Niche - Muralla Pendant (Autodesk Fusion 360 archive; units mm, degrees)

design "Murralla" references "Niche - Chief Architect - Luxe Single Pendant Cordset", "Luxe Single Pendant Cordset - 4ft Standard", "Muralla"
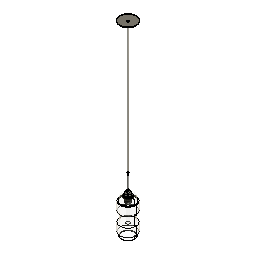
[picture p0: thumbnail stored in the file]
external_derived "ExternalDerived1"
external_derived "ExternalDerived2" bodies "Socket Body", "Shade Ring", "Shade Ring +Collar", "Socket", "Body1", "Metal Strain Relief", "Fabric Cord (1)", "Stem (Threaded)"
move "Move1"
external_derived "ExternalDerived3" bodies "T9-Bulb"
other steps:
derived_base_feature "Derived Base Feature1" bodies "Body8"
derived_base_feature "Derived Base Feature2" bodies "Socket Body", "Shade Ring", "Shade Ring +Collar", "Socket", "Body1", "Metal Strain Relief", "Fabric Cord (1)", "Stem (Threaded)"
derived_base_feature "Derived Base Feature3" bodies "T9-Bulb"
named bodies: "Body8", "Socket Body", "Shade Ring", "Shade Ring +Collar", "Socket", "Body1", "Metal Strain Relief", "Fabric Cord (1)", "Stem (Threaded)", "Cap (Threaded)", "T9-Bulb"

design "Luxe Single Pendant Cordset - 4ft Standard" references "Luxe Canopy - Single Pendant Cordset"
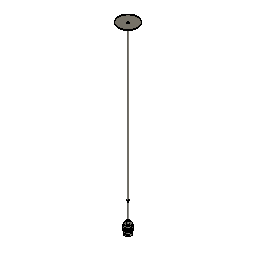
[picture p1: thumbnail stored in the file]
external_derived "ExternalDerived2" bodies "Cap (Threaded)"
move "Move1"
move "Move2"
offset_faces "OffsetFaces1" distance 1051.56
move "Move3"
move "Move4"
move "Move5"
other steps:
derived_base_feature "Derived Base Feature9" bodies "Socket Body", "Shade Ring", "Shade Ring +Collar", "Socket"
derived_base_feature "Derived Base Feature10" bodies "Body1"
derived_base_feature "Derived Base Feature12" bodies "Metal Strain Relief"
derived_base_feature "Derived Base Feature13" bodies "Fabric Cord (1)"
derived_base_feature "Derived Base Feature14" bodies "Stem (Threaded)"
derived_base_feature "Derived Base Feature15" bodies "Cap 9Threaded)", "Cap (Threaded)"
named bodies: "Socket Body", "Shade Ring", "Shade Ring +Collar", "Socket", "Metal Strain Relief", "Fabric Cord (1)", "Stem (Threaded)", "Cap 9Threaded)", "Body1", "Cap (Threaded)", "5M Set Screw"

design "Luxe Canopy - Single Pendant Cordset" references "Luxe Cordset", "Canopy Mounting Bar Screw", "M5 Set Screw", "Plastic Strain Relief", "Canopy Mounting Bar"
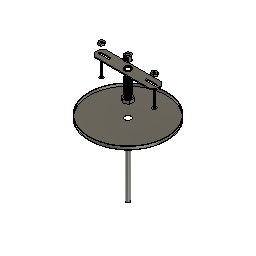
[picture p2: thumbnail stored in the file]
sketch "Sketch1" plane through (0, 0, 0) normal (0, 0, 1) x axis (1, 0, 0)
  circle C1 centre (0, 0) radius 63.5
  point P1 (0, 0)
  point P2 (0, 0)
  coincident P1 P2
  dimension "d1" diameter C1 = 127
extrude "Extrude1" new body sketch "Sketch1" along normal blind 5.08
shell "Shell1" innerThickness 0.762
hole "Hole1" HoleDepth 35.56 HoleDiameter 10.16 TipAngle 118
component_from_bodies "Body->Comp1"
component_insert "Component Insert1"
component_insert "Component Insert2"
component_insert "Component Insert3"
sketch "Sketch2" plane through (0, 0, 0) normal (0, 0, 1) x axis (1, 0, 0)
  circle C1 centre (0, 0) radius 3.175
  point P1 (0, 0)
  point P2 (0, 0)
  coincident P1 P2
  dimension "d8" diameter C1 = 6.35
extrude "Extrude2" new body sketch "Sketch2" along normal blind 127 and against normal blind 127 bodies "Fabric Cord"
component_insert "Component Insert4"
component_insert "Component Insert5"
position "Position1"
sketch "Sketch3" plane through (0, 0, 0.762) normal (0, 0, 1) x axis (-1, 0, 0)
  circle C1 centre (-0.0475, 0.2257) radius 5.08
  circle C2 centre (0, 0) radius 62.738
  circle C3 centre (0, 0) radius 4.826
  concentric C2 C3
  dimension "d13" diameter C3 = 9.652
extrude "Extrude3" new body sketch "Sketch3" profile of C3 along normal blind 25.4 bodies "Threaded Nipple"
shell "Shell2" innerThickness 1.27
thread "Thread1"
sketch "Sketch5" plane through (0, 0, 127) normal (0, 0, 1) x axis (-1, 0, 0)
  line L1 (-6.8191, 3.937) -> (0, 7.874)
  line L2 (-6.8191, -3.937) -> (-6.8191, 3.937)
  line L3 (0, -7.874) -> (-6.8191, -3.937)
  line L4 (6.8191, -3.937) -> (0, -7.874)
  line L5 (6.8191, 3.937) -> (6.8191, -3.937)
  line L6 (0, 7.874) -> (6.8191, 3.937)
  circle C1 centre (0, 0) radius 3.175
  point P2 (0, 0)
  point P9 (0, 0)
  point P3 (0, 7.874)
  coincident P2 P9
  dimension "d20" distance P3 P9 = 7.874
extrude "Extrude4" new body sketch "Sketch5" along normal blind 5.08 bodies "Hex Nut"
move "Move1"
thread "Thread2"
move "Move2" TranslateX 0 TranslateY 0 TranslateZ -55.88
move "Move3" TranslateX 0 TranslateY 0 TranslateZ 60.96
position "Position2"
sketch "Sketch6" plane through (0, 0, 0) normal (0, 0, 1) x axis (1, 0, 0)
  circle C1 centre (0, 0) radius 9.525
  point P1 (0, 0)
  point P2 (0, 0)
  coincident P1 P2
  dimension "d29" diameter C1 = 19.05
extrude "Extrude5" new body sketch "Sketch6" along normal blind 16.129 bodies "Metal Strain Relief"
move "Move4" TranslateX 0 TranslateY 0 TranslateZ -86.36
hole "Hole2" HoleDepth 10.16 HoleDiameter 5.08 TipAngle 118
hole "Hole3" HoleDepth 4.064 HoleDiameter 7.62 TipAngle 180
hole "Hole4" HoleDepth 12.192 HoleDiameter 9.144 TipAngle 180
thread "Thread3" ThreadOffset 0 ThreadLength 6.096
move "Move1" TranslateX 0 TranslateY 0 TranslateZ 68.58
move "Move5" TranslateX 0 TranslateY 0 TranslateZ 138.43
component_insert "Component Insert6"
external_derived "ExternalDerived1" bodies "5M Set Screw"
move "Move6" TranslateX 0 TranslateY 0 TranslateZ -185.42
copy_paste_bodies "CopyPasteBodies1"
move "Move7" TranslateX 0 TranslateY 0 TranslateZ -12.7
offset_faces "OffsetFaces1" distance -152.4
move "Move8"
component_from_bodies "Body->Comp2"
component_from_bodies "Body->Comp3"
component_from_bodies "Body->Comp4"
component_from_bodies "Body->Comp5"
hole "Hole1" HoleDepth 25.4 HoleDiameter 6.35 TipAngle 180
sketch "Sketch7" plane through (0, 0, 0) normal (0, 0, 1) x axis (1, 0, 0)
  line L1 (49.784, 3.9595) -> (52.07, 0)
  line L2 (45.212, 3.9595) -> (49.784, 3.9595)
  line L3 (42.926, 0) -> (45.212, 3.9595)
  line L4 (45.212, -3.9595) -> (42.926, 0)
  line L5 (49.784, -3.9595) -> (45.212, -3.9595)
  line L6 (52.07, 0) -> (49.784, -3.9595)
  point P2 (52.07, 0)
  point P8 (47.498, 0)
  dimension "d63" distance P2 P8 = 4.572
extrude "Extrude6" new body sketch "Sketch7" along normal blind 3.175 bodies "Mounting Hex Nut"
hole "Hole5" HoleDepth 25.4 HoleDiameter 3.81 TipAngle 180
thread "Thread4"
move "Move9"
component_from_bodies "Body->Comp6"
copy_paste "CopyPaste1"
move "Move10"
derived_base_feature "Derived Base Feature3" bodies "Stem (Threaded)", "Cap 9Threaded)"
move "Move11"
component_from_bodies "Body->Comp7"
component_from_bodies "Body->Comp8"
component_from_bodies "Body->Comp9"
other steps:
base_feature "Base Feature1"
base_feature "Base Feature1" bodies "Stem (Threaded)"
base_feature "Base Feature1" bodies "Cap 9Threaded)"
base_feature "Base Feature1" bodies "Fabric Cord"
base_feature "Base Feature1" bodies "Metal Strain Relief"
base_feature "Base Feature1" bodies "Mounting Hex Nut"
base_feature "Base Feature1" bodies "Hex Nut"
base_feature "Base Feature1" bodies "Fabric Cord (1)"
base_feature "Base Feature1" bodies "Threaded Nipple"
derived_base_feature "Derived Base Feature1" bodies "Socket Body", "Shade Ring", "Shade Ring +Collar", "Socket", "Rigid Stem"
derived_base_feature "Derived Base Feature2" bodies "5M Set Screw"
base_feature "Base Feature1" bodies "Fabric Cord", "Fabric Cord (1)"
create_component "CreateComponent1"
remove_body "RemoveBody1"
create_component "CreateComponent2"
remove_body "RemoveBody2"
create_component "CreateComponent3"
remove_body "RemoveBody3"
create_component "CreateComponent4"
remove_body "RemoveBody4"
create_component "CreateComponent5"
remove_body "RemoveBody5"
create_component "CreateComponent6"
remove_body "RemoveBody6"
create_component "CreateComponent7"
remove_body "RemoveBody7"
create_component "CreateComponent8"
remove_body "RemoveBody8"
create_component "CreateComponent9"
remove_body "RemoveBody9"
named bodies: "Fabric Cord", "Threaded Nipple", "Hex Nut", "Metal Strain Relief", "Socket Body", "Shade Ring", "Shade Ring +Collar", "Socket", "Rigid Stem", "5M Set Screw", "Fabric Cord (1)", "Mounting Hex Nut", "Stem (Threaded)", "Cap 9Threaded)"

design "Muralla" references "Niche_Muralla_Single_Pendant"
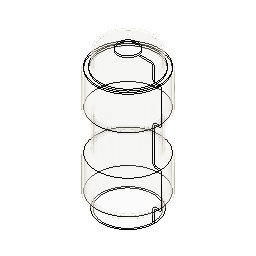
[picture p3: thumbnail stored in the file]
external_derived "ExternalDerived"
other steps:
derived_base_feature "Derived Base Feature" bodies "Body8"
named bodies: "Body8"

design "M5 Set Screw"
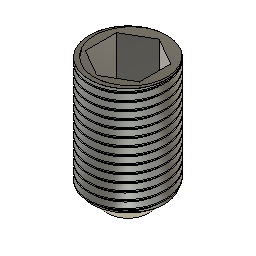
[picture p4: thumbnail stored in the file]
sketch "Sketch1" plane through (0, 0, 0) normal (0, 0, 1) x axis (1, 0, 0)
  circle C1 centre (0, 0) radius 2.5
  point P1 (0, 0)
  point P2 (0, 0)
  coincident P1 P2
  dimension "d1" diameter C1 = 5
extrude "Extrude1" new body sketch "Sketch1" along normal blind 8
sketch "Sketch2" plane through (0, 0, 8) normal (0, 0, 1) x axis (-1, 0, 0)
  line L1 (-1.7321, 1) -> (0, 2)
  line L2 (-1.7321, -1) -> (-1.7321, 1)
  line L3 (0, -2) -> (-1.7321, -1)
  line L4 (1.7321, -1) -> (0, -2)
  line L5 (1.7321, 1) -> (1.7321, -1)
  line L6 (0, 2) -> (1.7321, 1)
  circle C1 centre (0, 0) radius 2.5
  point P2 (0, 0)
  point P9 (0, 0)
  coincident P2 P9
extrude "Extrude2" cut sketch "Sketch2" profile of L1 L2 L3 L4 L5 L6 against normal blind 3
thread "Thread1" ThreadOffset 0.99 ThreadLength 7
chamfer "Chamfer1" distance 1.15

design "Luxe Cordset" references "M5 Set Screw"
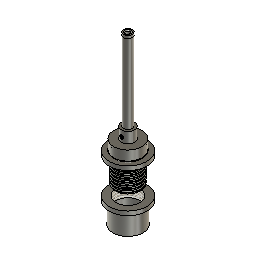
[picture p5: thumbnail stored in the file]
sketch "Sketch1" plane through (0, 0, 0) normal (0, 0, 1) x axis (1, 0, 0)
  circle C1 centre (0, 0) radius 20.6
  point P1 (0, 0)
  point P2 (0, 0)
  coincident P1 P2
  dimension "d11" diameter C1 = 41.2
extrude "Extrude1" new body sketch "Sketch1" along normal blind 14 bodies "Socket Body"
sketch "Sketch2" plane through (0, 0, 14) normal (0, 0, 1) x axis (-1, 0, 0)
  circle C1 centre (0, 0) radius 20.6
  circle C2 centre (0, 0) radius 9.6
  concentric C1 C2
  dimension "d3" diameter C2 = 19.2
extrude "Extrude2" add sketch "Sketch2" profile of C2 along normal blind 15.75
sketch "Sketch3" plane through (0, 0, 29.75) normal (0, 0, 1) x axis (-1, 0, 0)
  circle C1 centre (0, 0) radius 9.6
  circle C2 centre (0, 0) radius 5.75
  concentric C1 C2
  dimension "d6" diameter C2 = 11.5
extrude "Extrude3" new body sketch "Sketch3" profile of C2 along normal blind 114 bodies "Rigid Stem"
move "Move1"
sketch "Sketch4" plane through (0, 0, 203.75) normal (0, 0, 1) x axis (-1, 0, 0)
  circle C1 centre (0, 0) radius 5.75
  circle C2 centre (0, 0) radius 27.5
  dimension "d10" diameter C2 = 55
extrude "Extrude4" new body sketch "Sketch4" profile of C2 along normal blind 6 bodies "Shade Ring"
hole "Hole1" HoleDepth 25 HoleDiameter 42.75 TipAngle 118
sketch "Sketch5" plane through (0, 0, 0) normal (0, 0, 1) x axis (1, 0, 0)
  circle C1 centre (0, 0) radius 22
  point P1 (0, 0)
  point P2 (0, 0)
  coincident P1 P2
  dimension "d18" diameter C1 = 44
move "Move2"
copy_paste_bodies "CopyPasteBodies1"
move "Move3"
sketch "Sketch6" plane through (0, 0, 60) normal (0, 0, -1) x axis (1, 0, 0)
  circle C1 centre (0, 0) radius 20.6
  circle C2 centre (0, 0) radius 21.375
  circle C3 centre (0, 0) radius 20
  concentric C1 C2
  concentric C1 C3
  dimension "d21" diameter C2 = 42.75
  dimension "d24" diameter C3 = 40
cylinder_primitive "CylinderPrimitive1" Height 8 Diameter 42.75
thread "Thread1"
thread "Thread3"
hole "Hole2" HoleDepth 18 HoleDiameter 39 TipAngle 180
move "Move4"
move "Move5"
move "Move6"
hole "Hole3" HoleDepth 114 HoleDiameter 7.6 TipAngle 180
derived_base_feature "Derived Base Feature" bodies "Socket"
move "Move7"
scale "Scale1" ScaleX 1.2 ScaleY 1.2
move "Move8"
sketch "Sketch8" plane through (0, 0, -23.9827) normal (0, 0, -1) x axis (1, 0, 0)
  circle C1 centre (0, -0.036) radius 27.5
  circle C2 centre (0, -0.036) radius 22
  circle C3 centre (0, -0.036) radius 19.5
  dimension "d36" diameter C2 = 44
  dimension "d42" = -2.5
extrude "Extrude7" add sketch "Sketch8" profile of C2 C3 along normal blind 30
offset_faces "OffsetFaces1" distance 2.75
offset_faces "OffsetFaces2" distance -9
thread "Thread2"
move "Move9"
move "Move10"
move "Move11"
scale "Scale2" ScaleZ 1.2
move "Move12"
move "Move13"
move "Move14"
move "Move15"
move "Move16"
split_face "SplitFace1"
move "Move17"
move "Move18"
move "Move19"
move "Move20"
move "Move21"
move "Move22"
move "Move23"
move "Move24"
move "Move25"
move "Move26"
move "Move27"
thread "Thread4"
move "Move28"
move "Move29"
move "Move30"
hole "Hole4" HoleDepth 21 HoleDiameter 39.35 TipAngle 180
hole "Hole5" HoleDepth 9 HoleDiameter 5 TipAngle 180
move "Move31"
move "Move32"
hole "Hole6" HoleDepth 20 HoleDiameter 10 TipAngle 180
move_face "MoveFace3"
move "Move33"
move "Move34"
move "Move35"
move "Move36"
move "Move37"
thread "Thread5" ThreadOffset 0 ThreadLength 6
thread "Thread6" ThreadOffset 0 ThreadLength 6
move "Move38"
move "Move39"
move "Move40"
move "Move41"
component_insert "Component Insert"
thread "Thread7" ThreadOffset 0.5 ThreadLength 5.337
chamfer "Chamfer1" distance 0.5 distance 0.35
sketch "Sketch12" plane through (0, 0, 0) normal (0, 0, 1) x axis (1, 0, 0)
  circle C1 centre (0, 0) radius 6.35
  dimension "d60" diameter C1 = 12.7
extrude "Extrude8" new body sketch "Sketch12" along normal blind 115 bodies "Stem (Threaded)"
hole "Hole7" HoleDepth 115 HoleDiameter 9.65 TipAngle 118
thread "Thread8" ThreadOffset 0 ThreadLength 12.5
thread "Thread9" ThreadOffset 0 ThreadLength 12.5
sketch "Sketch13" plane through (0, 0, 0) normal (0, 0, 1) x axis (1, 0, 0)
  circle C1 centre (0, 0) radius 6.35
  point P1 (0, 0)
  point P2 (0, 0)
  coincident P1 P2
  dimension "d70" diameter C1 = 12.7
extrude "Extrude9" new body sketch "Sketch13" along normal blind 4 bodies "Cap 9Threaded)"
sketch "Sketch14" plane through (0, 0, 4) normal (0, 0, 1) x axis (-1, 0, 0)
  circle C1 centre (0, 0) radius 6.35
  circle C2 centre (0, 0) radius 4.5
  concentric C1 C2
  dimension "d73" diameter C2 = 9
extrude "Extrude10" add sketch "Sketch14" profile of C2 against normal blind 14
thread "Thread10"
hole "Hole8" HoleDepth 115 HoleDiameter 6.5 TipAngle 118 CSDiameter 9 CSAngle 90
move "Move42"
move "Move43"
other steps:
base_feature "Base Feature" bodies "Shade Ring +Collar"
named bodies: "Socket Body", "Shade Ring", "Shade Ring +Collar", "Socket", "Rigid Stem", "Stem (Threaded)", "Cap 9Threaded)"

design "Niche - Chief Architect - Luxe Single Pendant Cordset"
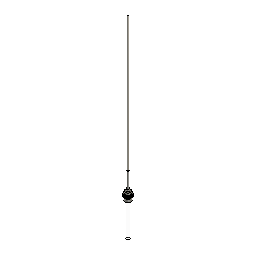
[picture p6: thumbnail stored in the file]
derived_base_feature "Derived Base Feature" bodies "Socket Body", "Shade Ring", "Shade Ring +Collar", "Socket", "Canopy", "Metal Strain Relief", "Fabric Cord (1)", "Stem (Threaded)"
remove_body "RemoveBody1"
remove_body "RemoveBody2"
split "Split1" bodies "Socket Body (1)"
remove_body "RemoveBody3"
align "Align1"
hole "Hole1" HoleDepth 19.05 HoleDiameter 8.89 TipAngle 118
combine "Combine1" bodies "Shade Ring"
split "Split2" bodies "Socket (1)"
remove_body "RemoveBody4"
split "Split3" bodies "Fabric Cord (1) (1)"
remove_body "RemoveBody5"
combine "Combine2" bodies "Socket Body"
align "Align2"
combine "Combine3" bodies "Metal Strain Relief"
sketch "Sketch1" plane through (0, 0, 0) normal (0, 1, 0) x axis (1, 0, 0)
  line L1 (13.1098, 24.9049) -> (-12.2902, 24.9049)
  line L2 (18.1898, 37.1766) -> (18.1898, 29.9849)
  line L3 (-17.3702, 29.9849) -> (-17.3702, 36.7132)
  line L4 (0, 132.969) -> (0, 24.9049)
  arc A1 centre (0, 86.36) radius 46.609 clockwise from (-22.6031, 45.5985) to (23.276, 45.979)
  arc A2 centre (-27.5302, 36.7132) radius 10.16 clockwise from (-22.6031, 45.5985) to (-17.3702, 36.7132)
  arc A3 centre (28.3498, 37.1766) radius 10.16 clockwise from (18.1898, 37.1766) to (23.276, 45.979)
  arc A4 centre (-12.2902, 29.9849) radius 5.08 clockwise from (-12.2902, 24.9049) to (-17.3702, 29.9849)
  arc A5 centre (13.1098, 29.9849) radius 5.08 clockwise from (18.1898, 29.9849) to (13.1098, 24.9049)
  point P5 (18.1898, 43.4469)
  point P3 (-17.3702, 24.9049)
  point P4 (18.1898, 24.9049)
  point P18 (0, 24.9049)
  point P19 (0, 132.969)
  horizontal L1
  vertical L2
  vertical L3
  tangent A1 A2
  tangent L3 A2
  coincident P5 L2
  coincident P5 A1
  tangent L2 A3
  tangent A1 A3
  equal A2 A3
  coincident P3 L1
  coincident P3 L3
  tangent L1 A4
  tangent L3 A4
  coincident P4 L1
  coincident P4 L2
  tangent L1 A5
  tangent L2 A5
  coincident L1 P18
  coincident A1 P19
  perpendicular L1 L4
  dimension "d4" diameter A1 = 93.218
  dimension "d5" distance P3 P4 = 35.56
  dimension "d6" distance P4 P5 = 18.542
  dimension "d7" radius A2 = 10.16
  dimension "d8" radius A4 = 5.08
  dimension "d9" radius A5 = 5.08
revolve "Revolve1" sketch "Sketch1" AlongAngle 360 bodies "G30-Bulb"
move "Move1"
sketch "Sketch2" plane through (0, 0, 0) normal (0, 1, 0) x axis (1, 0, 0)
  line L1 (12.7, 0) -> (-12.7, 0)
  line L2 (12.7, 152.4) -> (12.7, 0)
  line L3 (-12.7, 0) -> (-12.7, 152.4)
  line L4 (0, 165.1) -> (0, 0)
  arc A1 centre (0, 152.4) radius 12.7 clockwise from (-12.7, 152.4) to (12.7, 152.4)
  point P1 (0, 0)
  point P7 (0, 0)
  point P8 (0, 165.1)
  horizontal L1
  vertical L2
  vertical L3
  coincident P1 P7
  midpoint A1 P8
  perpendicular L1 L4
revolve "Revolve2" sketch "Sketch2" AlongAngle 360 bodies "T9-Bulb"
move "Move2"
sketch "Sketch3" plane through (0, 0, 0) normal (0, 1, 0) x axis (1, 0, 0)
  line L1 (12.7, 0) -> (-12.7, 0)
  line L2 (12.7, 254) -> (12.7, 0)
  line L3 (-12.7, 0) -> (-12.7, 254)
  line L4 (0, 266.7) -> (0, 0)
  arc A1 centre (0, 254) radius 12.7 clockwise from (-12.7, 254) to (12.7, 254)
  point P1 (0, 0)
  point P7 (0, 0)
  point P8 (0, 266.7)
  horizontal L1
  vertical L2
  vertical L3
  coincident P1 P7
  midpoint A1 P8
  perpendicular L1 L4
revolve "Revolve3" sketch "Sketch3" AlongAngle 360 bodies "T8-Bulb"
move "Move3"
move "Move4"
move "Move5"
sketch "Sketch4" plane through (0, 0, 0) normal (0, 1, 0) x axis (1, 0, 0)
  line L1 (15.875, -8.763) -> (-15.875, -8.763)
  line L2 (15.875, 22.987) -> (15.875, -8.763)
  line L3 (-15.875, 22.987) -> (15.875, 22.987)
  line L4 (-15.875, -8.763) -> (-15.875, 22.987)
  line L5 (0, 22.987) -> (0, -8.763)
  point P6 (0, -8.763)
  point P7 (0, 22.987)
  point P2 (-15.875, -8.763)
  point P3 (15.875, -8.763)
  point P5 (-15.875, 22.987)
  horizontal L1
  vertical L2
  horizontal L3
  vertical L4
  midpoint L1 P6
  midpoint L3 P7
  dimension "d13" distance P2 P3 = 31.75
  dimension "d14" distance P2 P5 = 31.75
revolve "Revolve4" sketch "Sketch4" AlongAngle 360 bodies "Bulb Extender"
move "Move6"
sketch "Sketch5" plane through (0, 0, 0) normal (0, 1, 0) x axis (1, 0, 0)
  line L1 (-12.7, 35.56) -> (12.7, 35.56)
  line L2 (-12.7, 5.08) -> (-12.7, 35.56)
  line L3 (12.7, 5.08) -> (-12.7, 5.08)
  line L4 (12.7, 35.56) -> (12.7, 5.08)
  line L5 (-12.7, 5.08) -> (12.7, 35.56)
  line L6 (12.7, 5.08) -> (-12.7, 35.56)
  line L7 (0, 35.56) -> (0, 5.08)
  point P6 (0, 20.32)
  point P7 (0, 5.08)
  point P8 (0, 35.56)
  horizontal L1
  perpendicular L1 L2
  parallel L1 L3
  parallel L2 L4
  coincident L5 P6
  coincident L6 P6
  midpoint L3 P7
  midpoint L1 P8
revolve "Revolve5" sketch "Sketch5" AlongAngle 360 bodies "Y-Spliter"
sketch "Sketch6" plane through (0, 0, 0) normal (0, 1, 0) x axis (1, 0, 0)
  line L1 (-55.88, 64.9514) -> (-21.59, 64.9514)
  line L2 (-55.88, 35.7414) -> (-55.88, 64.9514)
  line L3 (-21.59, 35.7414) -> (-55.88, 35.7414)
  line L4 (-21.59, 64.9514) -> (-21.59, 35.7414)
  line L5 (-55.88, 35.7414) -> (-21.59, 64.9514)
  line L6 (-21.59, 35.7414) -> (-55.88, 64.9514)
  line L7 (-38.735, 64.9514) -> (-38.735, 35.7414)
  point P6 (-38.735, 50.3464)
  point P7 (-38.735, 35.7414)
  point P8 (-38.735, 64.9514)
  point P4 (-55.88, 35.7414)
  point P5 (-21.59, 35.7414)
  point P2 (-21.59, 64.9514)
  horizontal L1
  perpendicular L1 L2
  parallel L1 L3
  parallel L2 L4
  coincident L5 P6
  coincident L6 P6
  midpoint L3 P7
  midpoint L1 P8
  dimension "d17" distance P4 P5 = 34.29
  dimension "d18" distance P2 P5 = 29.21
revolve "Revolve6" sketch "Sketch6" AlongAngle 360
chamfer "Chamfer1" distance 7.62
move "Move7"
mirror "Mirror1" mirrorStitchTolerance 0.1016
move "Move8"
combine "Combine4"
move "Move9"
sketch "Sketch7" plane through (0, 0, 0) normal (0, 1, 0) x axis (1, 0, 0)
  line L1 (-15.24, 40.64) -> (-15.24, 48.1816)
  line L2 (12.7, 38.1) -> (-12.7, 38.1)
  line L3 (15.24, 48.1816) -> (15.24, 40.64)
  line L4 (0, 100.1623) -> (0, 38.1)
  arc A1 centre (0, 76.2) radius 23.9623 clockwise from (-19.7282, 62.5988) to (19.7282, 62.5988)
  arc A2 centre (-40.64, 48.1816) radius 25.4 clockwise from (-19.7282, 62.5988) to (-15.24, 48.1816)
  arc A3 centre (40.64, 48.1816) radius 25.4 clockwise from (15.24, 48.1816) to (19.7282, 62.5988)
  arc A4 centre (-12.7, 40.64) radius 2.54 clockwise from (-12.7, 38.1) to (-15.24, 40.64)
  arc A5 centre (12.7, 40.64) radius 2.54 clockwise from (15.24, 40.64) to (12.7, 38.1)
  point P15 (0, 38.1)
  point P16 (0, 100.1623)
  parallel L1 L3
  tangent A1 A2
  tangent L1 A2
  tangent A1 A3
  tangent L3 A3
  tangent L1 A4
  tangent L2 A4
  tangent L2 A5
  tangent L3 A5
  midpoint L2 P15
  midpoint A1 P16
  perpendicular L2 L4
  dimension "d23" radius A2 = 25.4
  dimension "d24" radius A3 = 25.4
  dimension "d25" radius A4 = 2.54
  dimension "d26" radius A5 = 2.54
revolve "Revolve7" sketch "Sketch7" AlongAngle 360 bodies "A15-Bulb"
move "Move10"
copy_paste_bodies "CopyPasteBodies1"
copy_paste_bodies "CopyPasteBodies2"
move "Move11"
mirror "Mirror2" mirrorStitchTolerance 0.1016 bodies "A15-Bulb (1) (1)"
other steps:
base_feature "Base Feature1" bodies "Y-Spliter", "Bulb Extender", "Y-Spliter (1)", "Bulb Extender (1)"
base_feature "Base Feature2" bodies "A15-Bulb", "A15-Bulb (1)"
named bodies: "Socket Body", "Shade Ring", "Shade Ring +Collar", "Socket", "Canopy", "Metal Strain Relief", "Fabric Cord (1)", "Stem (Threaded)", "Adapter", "5M Set Screw", "Body1 (1)", "Socket Body (1)", "Socket (1)", "Fabric Cord (1) (1)", "G30-Bulb", "T9-Bulb", "T8-Bulb", "Bulb Extender", "Y-Spliter", "A15-Bulb", "Y-Spliter (1)", "Bulb Extender (1)", "A15-Bulb (1)", "A15-Bulb (1) (1)"

design "Plastic Strain Relief"
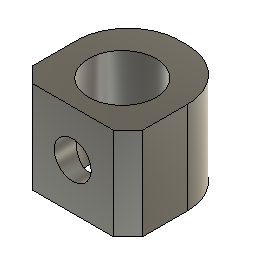
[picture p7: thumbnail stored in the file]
base_feature "Base Feature" bodies "strainrelief"
named bodies: "strainrelief"

design "Niche_Muralla_Single_Pendant"
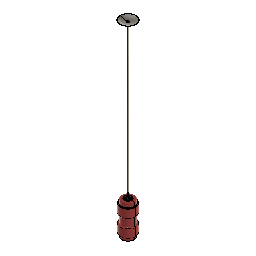
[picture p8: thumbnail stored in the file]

design "Canopy Mounting Bar Screw"
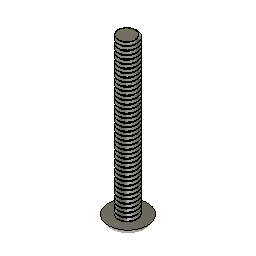
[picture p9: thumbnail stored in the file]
base_feature "Base Feature" bodies "screw1"
named bodies: "screw1"

design "Canopy Mounting Bar"
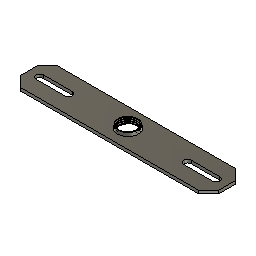
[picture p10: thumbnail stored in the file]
base_feature "Base Feature" bodies "mountingbar"
named bodies: "mountingbar"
